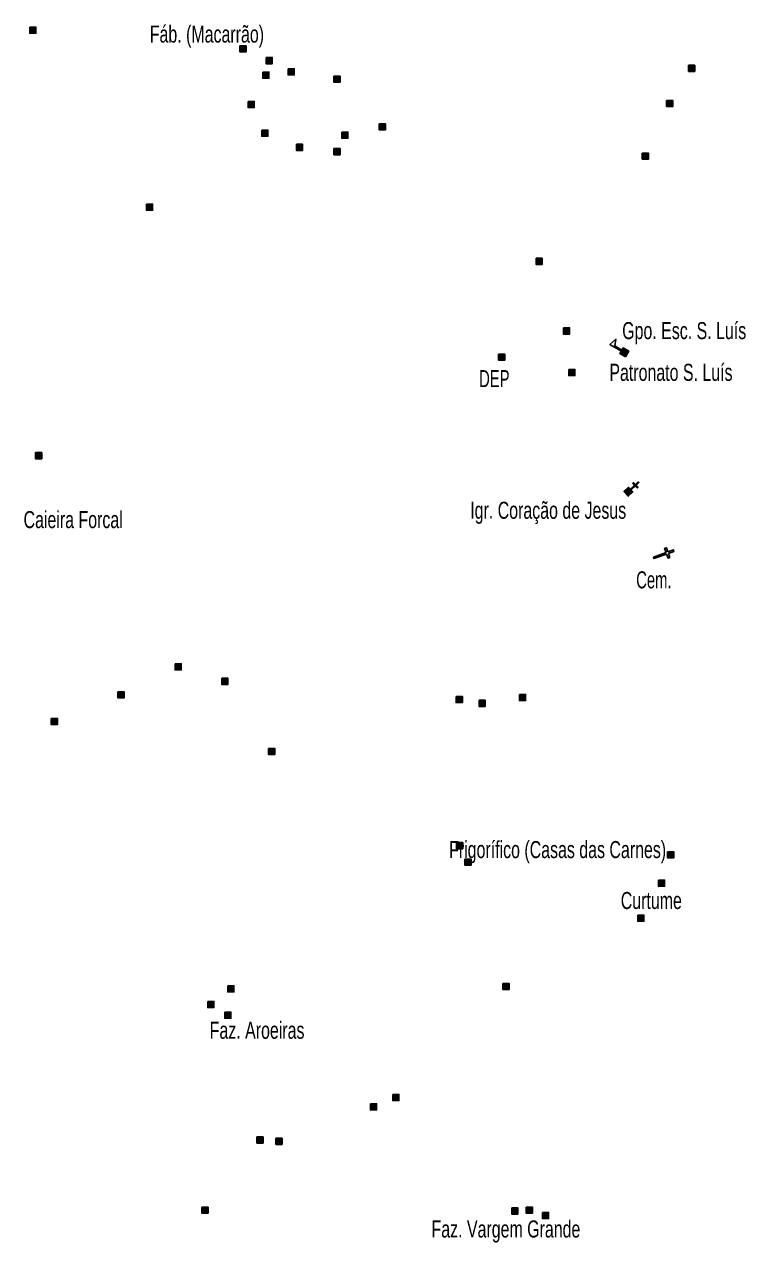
# Model space of a CAD drawing. Extents: x 447.8 to 473.9, y 7733.1 to 7760.8.
# Drawn here: x 451.43 to 454.82, y 7734.01 to 7739.73 of the extents above; entities that cross this region are included whole.
import ezdxf
from ezdxf.enums import TextEntityAlignment as Align

# ---------------------------------------------------------------- set-up
doc = ezdxf.new("R2010")
doc.units = 0
doc.header["$LTSCALE"] = 0.032
for name, color, linetype, lineweight in [('2', 7, 'Continuous', 25), ('20', 7, 'Continuous', 25), ('4', 7, 'Continuous', 25), ('6', 7, 'Continuous', 25)]:
    doc.layers.add(name, color=color, linetype=linetype, lineweight=lineweight)
doc.layers.add('61', color=7, linetype='Continuous')

msp = doc.modelspace()

# ---------------------------------------------------------------- hatches: boundary and pattern name
at = {"layer": '2'}
for points in [[(451.4577, 7739.717), (451.4867, 7739.717), (451.4867, 7739.688), (451.4577, 7739.688)], [(452.4447, 7739.6292), (452.4737, 7739.6292), (452.4737, 7739.6002), (452.4447, 7739.6002)], [(452.5683, 7739.5742), (452.5973, 7739.5742), (452.5973, 7739.5452), (452.5683, 7739.5452)], [(452.5523, 7739.5056), (452.5813, 7739.5056), (452.5813, 7739.4766), (452.5523, 7739.4766)], [(452.6712, 7739.5215), (452.7002, 7739.5215), (452.7002, 7739.4925), (452.6712, 7739.4925)], [(452.8865, 7739.4872), (452.9155, 7739.4872), (452.9155, 7739.4582), (452.8865, 7739.4582)], [(454.5528, 7739.5376), (454.5818, 7739.5376), (454.5818, 7739.5086), (454.5528, 7739.5086)], [(452.4836, 7739.3682), (452.5126, 7739.3682), (452.5126, 7739.3392), (452.4836, 7739.3392)], [(454.4498, 7739.3728), (454.4788, 7739.3728), (454.4788, 7739.3438), (454.4498, 7739.3438)], [(453.0993, 7739.2629), (453.1283, 7739.2629), (453.1283, 7739.2339), (453.0993, 7739.2339)], [(452.5477, 7739.2332), (452.5767, 7739.2332), (452.5767, 7739.2042), (452.5477, 7739.2042)], [(452.9231, 7739.224), (452.9521, 7739.224), (452.9521, 7739.195), (452.9231, 7739.195)], [(452.7102, 7739.1668), (452.7392, 7739.1668), (452.7392, 7739.1378), (452.7102, 7739.1378)], [(452.8865, 7739.1462), (452.9155, 7739.1462), (452.9155, 7739.1172), (452.8865, 7739.1172)], [(454.3353, 7739.1256), (454.3643, 7739.1256), (454.3643, 7739.0966), (454.3353, 7739.0966)], [(452.0057, 7738.8855), (452.0347, 7738.8855), (452.0347, 7738.8565), (452.0057, 7738.8565)], [(453.8364, 7738.6312), (453.8654, 7738.6312), (453.8654, 7738.6022), (453.8364, 7738.6022)], [(453.965, 7738.3044), (453.994, 7738.3044), (453.994, 7738.2754), (453.965, 7738.2754)], [(453.66, 7738.1811), (453.689, 7738.1811), (453.689, 7738.1521), (453.66, 7738.1521)], [(453.9897, 7738.1094), (454.0187, 7738.1094), (454.0187, 7738.0804), (453.9897, 7738.0804)], [(451.485, 7737.7186), (451.514, 7737.7186), (451.514, 7737.6896), (451.485, 7737.6896)], [(452.1403, 7736.7269), (452.1693, 7736.7269), (452.1693, 7736.6979), (452.1403, 7736.6979)], [(452.36, 7736.6582), (452.389, 7736.6582), (452.389, 7736.6292), (452.36, 7736.6292)], [(451.8721, 7736.5953), (451.9011, 7736.5953), (451.9011, 7736.5663), (451.8721, 7736.5663)], [(453.461, 7736.5735), (453.49, 7736.5735), (453.49, 7736.5445), (453.461, 7736.5445)], [(453.7585, 7736.5827), (453.7875, 7736.5827), (453.7875, 7736.5537), (453.7585, 7736.5537)], [(453.5686, 7736.5552), (453.5976, 7736.5552), (453.5976, 7736.5262), (453.5686, 7736.5262)], [(451.5586, 7736.4699), (451.5876, 7736.4699), (451.5876, 7736.4409), (451.5586, 7736.4409)], [(452.5798, 7736.3286), (452.6088, 7736.3286), (452.6088, 7736.2996), (452.5798, 7736.2996)], [(453.4633, 7735.8869), (453.4923, 7735.8869), (453.4923, 7735.8579), (453.4633, 7735.8579)], [(454.4543, 7735.8434), (454.4833, 7735.8434), (454.4833, 7735.8144), (454.4543, 7735.8144)], [(453.5022, 7735.8091), (453.5312, 7735.8091), (453.5312, 7735.7801), (453.5022, 7735.7801)], [(454.4109, 7735.7106), (454.4399, 7735.7106), (454.4399, 7735.6816), (454.4109, 7735.6816)], [(454.3139, 7735.5457), (454.3429, 7735.5457), (454.3429, 7735.5167), (454.3139, 7735.5167)], [(452.3875, 7735.214), (452.4165, 7735.214), (452.4165, 7735.185), (452.3875, 7735.185)], [(453.6807, 7735.2254), (453.7097, 7735.2254), (453.7097, 7735.1964), (453.6807, 7735.1964)], [(452.2937, 7735.1407), (452.3227, 7735.1407), (452.3227, 7735.1117), (452.2937, 7735.1117)], [(452.3738, 7735.0904), (452.4028, 7735.0904), (452.4028, 7735.0614), (452.3738, 7735.0614)], [(453.1634, 7734.7035), (453.1924, 7734.7035), (453.1924, 7734.6745), (453.1634, 7734.6745)], [(453.0581, 7734.6601), (453.0871, 7734.6601), (453.0871, 7734.6311), (453.0581, 7734.6311)], [(452.5248, 7734.5044), (452.5538, 7734.5044), (452.5538, 7734.4754), (452.5248, 7734.4754)], [(452.6141, 7734.4975), (452.6431, 7734.4975), (452.6431, 7734.4685), (452.6141, 7734.4685)], [(452.2662, 7734.1748), (452.2952, 7734.1748), (452.2952, 7734.1458), (452.2662, 7734.1458)], [(453.7219, 7734.1702), (453.7509, 7734.1702), (453.7509, 7734.1412), (453.7219, 7734.1412)], [(453.7906, 7734.1748), (453.8196, 7734.1748), (453.8196, 7734.1458), (453.7906, 7734.1458)], [(453.8661, 7734.1496), (453.8951, 7734.1496), (453.8951, 7734.1206), (453.8661, 7734.1206)]]:
    msp.add_hatch(color=256, dxfattribs=at).paths.add_polyline_path(points)
at = {"layer": '4'}
msp.add_hatch(color=256, dxfattribs=at).paths.add_polyline_path([(454.2565, 7738.1689), (454.2307, 7738.1842), (454.246, 7738.21), (454.2718, 7738.1947)])
at = {"layer": '6'}
for points in [[(454.271, 7737.5556), (454.2492, 7737.535), (454.2698, 7737.5132), (454.2916, 7737.5338)], [(454.2831, 7737.5429), (454.2796, 7737.5465), (454.2996, 7737.5654), (454.291, 7737.5745), (454.2947, 7737.5779), (454.3033, 7737.5688), (454.316, 7737.5808), (454.3194, 7737.5772), (454.3067, 7737.5652), (454.3153, 7737.5561), (454.3116, 7737.5526), (454.3031, 7737.5617)]]:
    msp.add_hatch(color=256, dxfattribs=at).paths.add_polyline_path(points)

# ---------------------------------------------------------------- linework, layer by layer
at = {"layer": '2'}
for points in [[(451.4577, 7739.717), (451.4867, 7739.717), (451.4867, 7739.688), (451.4577, 7739.688)], [(452.4447, 7739.6292), (452.4737, 7739.6292), (452.4737, 7739.6002), (452.4447, 7739.6002)], [(452.5683, 7739.5742), (452.5973, 7739.5742), (452.5973, 7739.5452), (452.5683, 7739.5452)], [(452.5523, 7739.5056), (452.5813, 7739.5056), (452.5813, 7739.4766), (452.5523, 7739.4766)], [(452.6712, 7739.5215), (452.7002, 7739.5215), (452.7002, 7739.4925), (452.6712, 7739.4925)], [(452.8865, 7739.4872), (452.9155, 7739.4872), (452.9155, 7739.4582), (452.8865, 7739.4582)], [(454.5528, 7739.5376), (454.5818, 7739.5376), (454.5818, 7739.5086), (454.5528, 7739.5086)], [(452.4836, 7739.3682), (452.5126, 7739.3682), (452.5126, 7739.3392), (452.4836, 7739.3392)], [(454.4498, 7739.3728), (454.4788, 7739.3728), (454.4788, 7739.3438), (454.4498, 7739.3438)], [(453.0993, 7739.2629), (453.1283, 7739.2629), (453.1283, 7739.2339), (453.0993, 7739.2339)], [(452.5477, 7739.2332), (452.5767, 7739.2332), (452.5767, 7739.2042), (452.5477, 7739.2042)], [(452.9231, 7739.224), (452.9521, 7739.224), (452.9521, 7739.195), (452.9231, 7739.195)], [(452.7102, 7739.1668), (452.7392, 7739.1668), (452.7392, 7739.1378), (452.7102, 7739.1378)], [(452.8865, 7739.1462), (452.9155, 7739.1462), (452.9155, 7739.1172), (452.8865, 7739.1172)], [(454.3353, 7739.1256), (454.3643, 7739.1256), (454.3643, 7739.0966), (454.3353, 7739.0966)], [(452.0057, 7738.8855), (452.0347, 7738.8855), (452.0347, 7738.8565), (452.0057, 7738.8565)], [(453.8364, 7738.6312), (453.8654, 7738.6312), (453.8654, 7738.6022), (453.8364, 7738.6022)], [(453.965, 7738.3044), (453.994, 7738.3044), (453.994, 7738.2754), (453.965, 7738.2754)], [(453.66, 7738.1811), (453.689, 7738.1811), (453.689, 7738.1521), (453.66, 7738.1521)], [(453.9897, 7738.1094), (454.0187, 7738.1094), (454.0187, 7738.0804), (453.9897, 7738.0804)], [(451.485, 7737.7186), (451.514, 7737.7186), (451.514, 7737.6896), (451.485, 7737.6896)], [(452.1403, 7736.7269), (452.1693, 7736.7269), (452.1693, 7736.6979), (452.1403, 7736.6979)], [(452.36, 7736.6582), (452.389, 7736.6582), (452.389, 7736.6292), (452.36, 7736.6292)], [(451.8721, 7736.5953), (451.9011, 7736.5953), (451.9011, 7736.5663), (451.8721, 7736.5663)], [(453.461, 7736.5735), (453.49, 7736.5735), (453.49, 7736.5445), (453.461, 7736.5445)], [(453.7585, 7736.5827), (453.7875, 7736.5827), (453.7875, 7736.5537), (453.7585, 7736.5537)], [(453.5686, 7736.5552), (453.5976, 7736.5552), (453.5976, 7736.5262), (453.5686, 7736.5262)], [(451.5586, 7736.4699), (451.5876, 7736.4699), (451.5876, 7736.4409), (451.5586, 7736.4409)], [(452.5798, 7736.3286), (452.6088, 7736.3286), (452.6088, 7736.2996), (452.5798, 7736.2996)], [(453.4633, 7735.8869), (453.4923, 7735.8869), (453.4923, 7735.8579), (453.4633, 7735.8579)], [(454.4543, 7735.8434), (454.4833, 7735.8434), (454.4833, 7735.8144), (454.4543, 7735.8144)], [(453.5022, 7735.8091), (453.5312, 7735.8091), (453.5312, 7735.7801), (453.5022, 7735.7801)], [(454.4109, 7735.7106), (454.4399, 7735.7106), (454.4399, 7735.6816), (454.4109, 7735.6816)], [(454.3139, 7735.5457), (454.3429, 7735.5457), (454.3429, 7735.5167), (454.3139, 7735.5167)], [(452.3875, 7735.214), (452.4165, 7735.214), (452.4165, 7735.185), (452.3875, 7735.185)], [(453.6807, 7735.2254), (453.7097, 7735.2254), (453.7097, 7735.1964), (453.6807, 7735.1964)], [(452.2937, 7735.1407), (452.3227, 7735.1407), (452.3227, 7735.1117), (452.2937, 7735.1117)], [(452.3738, 7735.0904), (452.4028, 7735.0904), (452.4028, 7735.0614), (452.3738, 7735.0614)], [(453.1634, 7734.7035), (453.1924, 7734.7035), (453.1924, 7734.6745), (453.1634, 7734.6745)], [(453.0581, 7734.6601), (453.0871, 7734.6601), (453.0871, 7734.6311), (453.0581, 7734.6311)], [(452.5248, 7734.5044), (452.5538, 7734.5044), (452.5538, 7734.4754), (452.5248, 7734.4754)], [(452.6141, 7734.4975), (452.6431, 7734.4975), (452.6431, 7734.4685), (452.6141, 7734.4685)], [(452.2662, 7734.1748), (452.2952, 7734.1748), (452.2952, 7734.1458), (452.2662, 7734.1458)], [(453.7219, 7734.1702), (453.7509, 7734.1702), (453.7509, 7734.1412), (453.7219, 7734.1412)], [(453.7906, 7734.1748), (453.8196, 7734.1748), (453.8196, 7734.1458), (453.7906, 7734.1458)], [(453.8661, 7734.1496), (453.8951, 7734.1496), (453.8951, 7734.1206), (453.8661, 7734.1206)]]:
    msp.add_lwpolyline(points, close=True, dxfattribs=at)
at = {"layer": '20'}
for points in [[(454.4551, 7737.2523), (454.4484, 7737.2711), (454.4404, 7737.2682), (454.4471, 7737.2494), (454.3874, 7737.2279)], [(454.4578, 7737.2448), (454.4842, 7737.2542), (454.4815, 7737.2618), (454.4551, 7737.2523)], [(454.3874, 7737.2279), (454.3901, 7737.2204), (454.4498, 7737.2419)], [(454.4498, 7737.2419), (454.4566, 7737.2231), (454.4646, 7737.2259), (454.4578, 7737.2448)]]:
    msp.add_lwpolyline(points, dxfattribs=at)
at = {"layer": '4'}
msp.add_line((454.2371, 7738.1949), (454.2397, 7738.1992), dxfattribs=at)
for points in [[(454.2371, 7738.1949), (454.1833, 7738.2268), (454.2119, 7738.2505), (454.2057, 7738.2194), (454.2397, 7738.1992)], [(454.2565, 7738.1689), (454.2307, 7738.1842), (454.246, 7738.21), (454.2718, 7738.1947)]]:
    msp.add_lwpolyline(points, close=True, dxfattribs=at)
at = {"layer": '6'}
for points in [[(454.271, 7737.5556), (454.2492, 7737.535), (454.2698, 7737.5132), (454.2916, 7737.5338)], [(454.2831, 7737.5429), (454.2796, 7737.5465), (454.2996, 7737.5654), (454.291, 7737.5745), (454.2947, 7737.5779), (454.3033, 7737.5688), (454.316, 7737.5808), (454.3194, 7737.5772), (454.3067, 7737.5652), (454.3153, 7737.5561), (454.3116, 7737.5526), (454.3031, 7737.5617)]]:
    msp.add_lwpolyline(points, close=True, dxfattribs=at)

# ---------------------------------------------------------------- texts
at = {"layer": '61'}
for s, width, p in [('Fáb. (Macarrão)', 0.7, (452.5583, 7739.6442)), ('Igr. Coração de Jesus', 0.7, (454.2597, 7737.4075)), ('Cem.', 0.65, (454.473, 7737.0806)), ('Frigorífico (Casas das Carnes)', 0.7, (454.4474, 7735.8137)), ('Curtume', 0.7, (454.5214, 7735.5746))]:
    msp.add_text(s, height=0.08, dxfattribs=dict(at, width=width)).set_placement(p, align=Align.RIGHT)
for s, width, p in [('Gpo. Esc. S. Luís', 0.7, (454.241, 7738.2513)), ('Patronato S. Luís', 0.7, (454.1808, 7738.0554)), ('DEP', 0.65, (453.5688, 7738.0258)), ('Caieira Forcal', 0.7, (451.4285, 7737.3636)), ('Faz. Aroeiras', 0.7, (452.303, 7734.9651)), ('Faz. Vargem Grande', 0.7, (453.3452, 7734.0316))]:
    msp.add_text(s, height=0.08, dxfattribs=dict(at, width=width)).set_placement(p)

doc.saveas('drawing.dxf')
